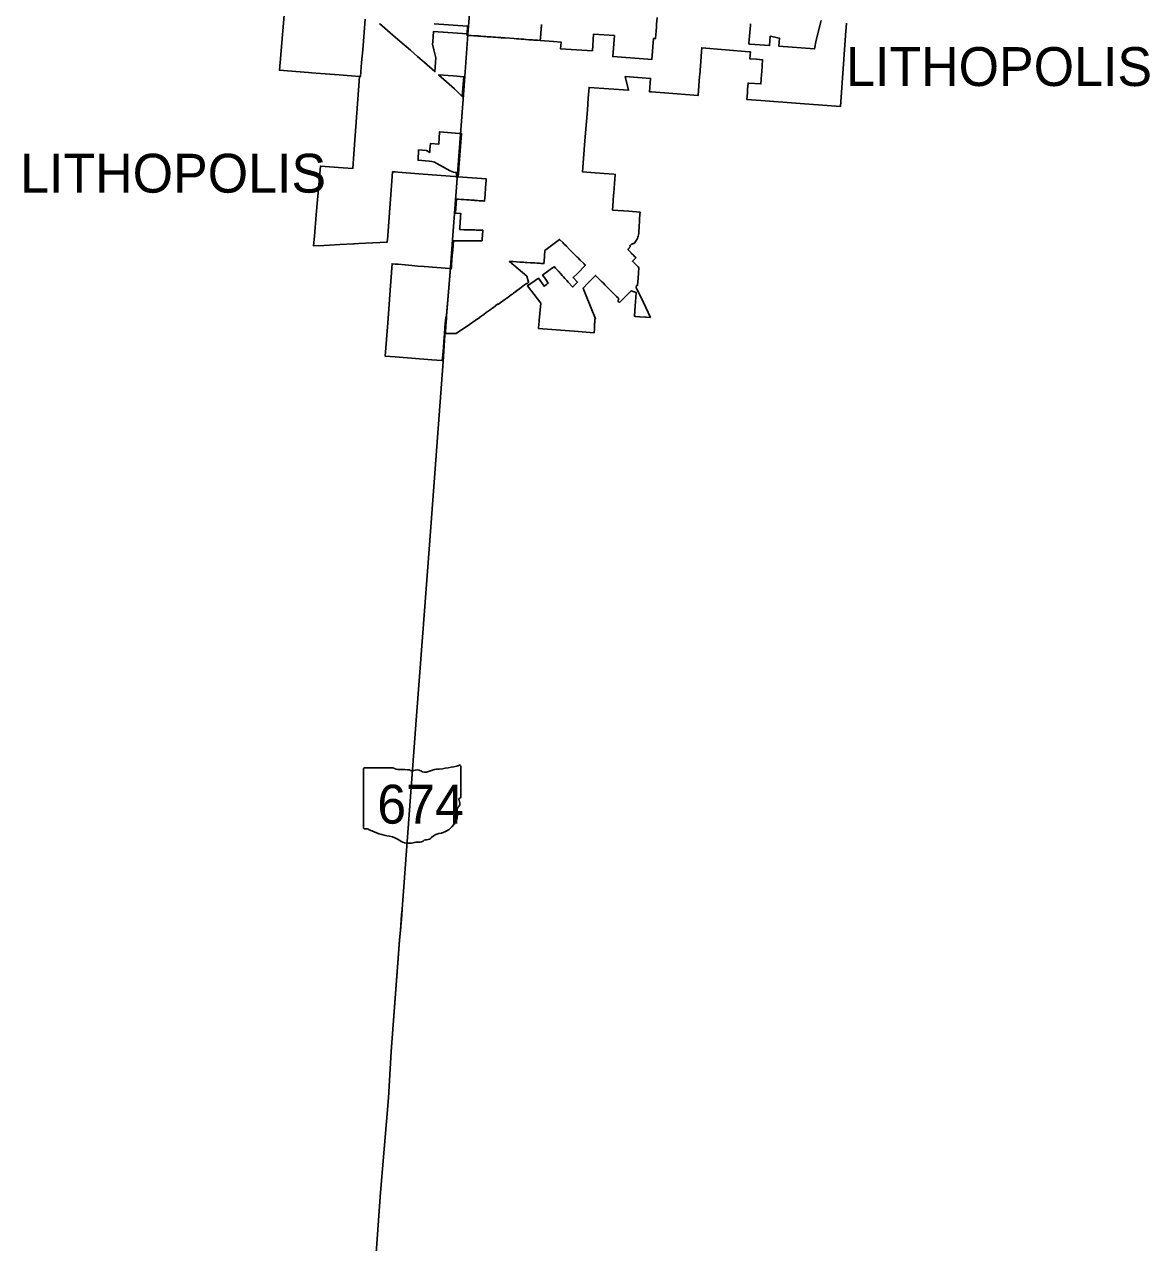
# Model space of a CAD drawing. Extents: x 1801177 to 2073177, y 551183 to 727183.
# Drawn here: x 1865307 to 1897750, y 628489 to 663604 of the extents above; entities that cross this region are included whole.
import ezdxf

# ---------------------------------------------------------------- set-up
doc = ezdxf.new("R2010")
doc.units = 0
for name, color, linetype in [('GM_X_Corporation', 7, 'Continuous'), ('GM_X_Corporation_Text', 7, 'Continuous'), ('GM_X_County', 7, 'Continuous'), ('GM_X_State_Location', 7, 'Continuous'), ('GM_X_State_Route', 7, 'Continuous'), ('GM_X_State_Shield', 7, 'Continuous')]:
    doc.layers.add(name, color=color, linetype=linetype)

msp = doc.modelspace()

# ---------------------------------------------------------------- linework, layer by layer
at = {"layer": 'GM_X_Corporation'}
for points in [[(1875134, 663754), (1875061, 662869), (1875031, 662503), (1874998, 662100), (1874967, 662103), (1874384, 662149), (1873849, 662191), (1873586, 662212), (1873499, 662218), (1872898, 662266), (1872661, 662284), (1872680, 662503), (1872831, 664211)], [(1889006, 663643), (1888980, 663285), (1888833, 661235), (1887677, 661322), (1886542, 661407), (1886138, 661437), (1886152, 661637), (1886160, 661736), (1886172, 661913), (1886186, 661912), (1886541, 661886), (1886561, 662164), (1886567, 662240), (1886592, 662585), (1886420, 662597), (1886223, 662611), (1886231, 662712), (1886238, 662812), (1886220, 662813), (1886208, 662814), (1886208, 662816), (1884836, 662928), (1884829, 662828), (1884817, 662668), (1884778, 662152), (1884776, 662113), (1884734, 661557), (1883761, 661631), (1883392, 661659), (1883362, 661661), (1883332, 661663), (1883360, 662044), (1882633, 662101), (1882726, 661706), (1881588, 661786), (1881564, 661474), (1881539, 661145), (1881470, 660252), (1881402, 659349), (1881762, 659323), (1882026, 659303), (1882299, 659283), (1882342, 659280), (1882323, 659020), (1882312, 658881), (1882311, 658868), (1882304, 658772), (1882297, 658682), (1882285, 658531), (1882284, 658508), (1882264, 658252), (1882264, 658251), (1882732, 658216), (1883057, 658192), (1883052, 658122), (1883043, 658002), (1883038, 657932), (1883042, 657931), (1883041, 657929), (1883046, 657928), (1883036, 657780), (1883023, 657614), (1883023, 657608), (1883019, 657572), (1883013, 657537), (1883004, 657503), (1882994, 657469), (1882981, 657435), (1882966, 657403), (1882949, 657372), (1882930, 657341), (1882908, 657313), (1882885, 657285), (1882874, 657295), (1882855, 657275), (1882848, 657268), (1882831, 657286), (1882781, 657236), (1882760, 657215), (1882778, 657197), (1882740, 657159), (1882743, 657156), (1882714, 657127), (1882717, 657124), (1882706, 657112), (1882723, 657095), (1882741, 657077), (1882770, 657048), (1882803, 657015), (1882806, 657012), (1882865, 656953), (1882892, 656926), (1882927, 656891), (1882939, 656879), (1882836, 656776), (1882999, 656614), (1883022, 656591), (1883011, 656437), (1883000, 656293), (1882985, 656081), (1882960, 656075), (1882949, 656023), (1883157, 655589), (1883358, 655155), (1883242, 655164), (1883230, 655165), (1883217, 655166), (1883056, 655178), (1882924, 655187), (1882894, 655189), (1882916, 655488), (1882925, 655605), (1882945, 655874), (1882801, 655925), (1882790, 655913), (1882731, 655854), (1882673, 655796), (1882638, 655761), (1882521, 655644), (1882515, 655638), (1882509, 655632), (1882472, 655593), (1882424, 655609), (1882433, 655710), (1882382, 655762), (1882101, 656041), (1882090, 656053), (1882063, 656080), (1882043, 656100), (1882003, 656140), (1881996, 656146), (1881990, 656153), (1881950, 656193), (1881910, 656232), (1881903, 656240), (1881775, 656368), (1881590, 656184), (1881541, 656135), (1881418, 656004), (1881448, 655927), (1881490, 655823), (1881770, 655116), (1881757, 655117), (1881751, 655009), (1881749, 654981), (1881741, 654832), (1881735, 654717), (1881163, 654759), (1880768, 654788), (1880134, 654838), (1880143, 654968), (1880148, 655027), (1880152, 655069), (1880168, 655269), (1880193, 655572), (1880193, 655572), (1879815, 656070), (1880127, 656292), (1880292, 656058), (1880359, 656108), (1880389, 656131), (1880395, 656135), (1880412, 656148), (1880412, 656148), (1880342, 656247), (1880301, 656306), (1880249, 656379), (1880281, 656402), (1880426, 656510), (1880507, 656569), (1880551, 656601), (1880581, 656624), (1880621, 656580), (1880656, 656542), (1880693, 656501), (1880698, 656495), (1880733, 656457), (1880745, 656444), (1880757, 656430), (1880760, 656427), (1880768, 656418), (1880773, 656413), (1880814, 656368), (1880854, 656324), (1880894, 656280), (1880938, 656232), (1880948, 656220), (1880989, 656176), (1881115, 656042), (1881122, 656035), (1881151, 656065), (1881190, 656106), (1881223, 656140), (1881257, 656174), (1881254, 656177), (1881128, 656310), (1881250, 656426), (1881483, 656660), (1881448, 656695), (1881435, 656707), (1881331, 656811), (1881261, 656881), (1881249, 656892), (1881061, 657079), (1881026, 657114), (1880934, 657207), (1880865, 657276), (1880841, 657301), (1880829, 657313), (1880736, 657406), (1880316, 657084), (1880292, 656769), (1880288, 656725), (1880287, 656709), (1880195, 656714), (1880155, 656717), (1880147, 656717), (1880136, 656718), (1880095, 656721), (1880013, 656726), (1879995, 656727), (1879951, 656730), (1879895, 656733), (1879796, 656740), (1879790, 656740), (1879744, 656743), (1879696, 656746), (1879654, 656749), (1879630, 656750), (1879596, 656753), (1879496, 656759), (1879396, 656765), (1879297, 656773), (1879294, 656773), (1879790, 656345), (1879844, 656171), (1879846, 656166), (1879821, 656148), (1879785, 656123), (1879783, 656133), (1879731, 656096), (1879678, 656058), (1879588, 655994), (1879495, 655928), (1879501, 655920), (1879413, 655857), (1879379, 655832), (1879356, 655816), (1879281, 655762), (1879264, 655750), (1879257, 655745), (1879146, 655664), (1879136, 655657), (1879135, 655656), (1879116, 655642), (1879109, 655637), (1879095, 655627), (1879025, 655576), (1878974, 655539), (1878968, 655547), (1878900, 655497), (1878894, 655493), (1878831, 655447), (1878789, 655416), (1878762, 655397), (1878722, 655367), (1878694, 655346), (1878675, 655333), (1878625, 655296), (1878556, 655246), (1878471, 655184), (1878382, 655119), (1878372, 655112), (1878075, 654905), (1877797, 654718), (1877756, 654694), (1877446, 654695), (1877452, 654778), (1877452, 654783), (1877458, 654866), (1877462, 654924), (1877469, 655016), (1877476, 655129), (1877478, 655166), (1877454, 655166), (1877445, 655040), (1877442, 655003), (1877417, 654690), (1877399, 654455), (1877387, 654301), (1877378, 654186), (1877363, 653986), (1877357, 653914), (1877348, 653915), (1877052, 653937), (1875999, 654017), (1875714, 654039), (1875785, 655003), (1875862, 656064), (1875871, 656190), (1875908, 656703), (1875999, 656696), (1876085, 656688), (1876285, 656671), (1876482, 656654), (1876656, 656639), (1876832, 656625), (1877562, 656567), (1877616, 656563), (1877619, 656598), (1877622, 656644), (1877626, 656698), (1877633, 656783), (1877634, 656797), (1877645, 656947), (1877657, 657097), (1877678, 657368), (1877949, 657368), (1878049, 657368), (1878149, 657368), (1878250, 657367), (1878351, 657367), (1878451, 657367), (1878505, 657367), (1878509, 657428), (1878514, 657517), (1878524, 657672), (1878423, 657675), (1878396, 657675), (1878374, 657676), (1878348, 657676), (1878340, 657677), (1878294, 657678), (1878287, 657678), (1878274, 657678), (1878214, 657679), (1878199, 657680), (1878134, 657681), (1878124, 657681), (1878054, 657683), (1878049, 657683), (1878001, 657684), (1877974, 657685), (1877856, 657687), (1877858, 657716), (1877860, 657746), (1877861, 657755), (1877870, 657883), (1877872, 657915), (1877873, 657920), (1877875, 657955), (1877877, 657984), (1877878, 657994), (1877884, 658074), (1877890, 658154), (1877848, 658156), (1877746, 658160), (1877738, 658160), (1877736, 658160), (1877767, 658568), (1877777, 658567), (1877814, 658565), (1877825, 658564), (1877893, 658559), (1877925, 658557), (1877973, 658554), (1878053, 658548), (1878055, 658548), (1878133, 658543), (1878177, 658539), (1878213, 658537), (1878274, 658533), (1878292, 658532), (1878372, 658526), (1878423, 658522), (1878452, 658520), (1878493, 658518), (1878532, 658515), (1878575, 658512), (1878576, 658530), (1878581, 658592), (1878589, 658704), (1878594, 658768), (1878599, 658827), (1878599, 658835), (1878605, 658916), (1878612, 659000), (1878621, 659120), (1878623, 659150), (1877815, 659206), (1877832, 659423), (1877836, 659483), (1877837, 659493), (1877845, 659592), (1877854, 659706), (1877911, 660458), (1877882, 660460), (1877853, 660462), (1877280, 660507), (1877266, 660327), (1877252, 660149), (1877013, 660169), (1877000, 660003), (1876993, 659908), (1876906, 659969), (1876674, 659987), (1876659, 659687), (1876981, 659663), (1877056, 659651), (1877128, 659629), (1877197, 659597), (1877581, 659380), (1877628, 659360), (1877677, 659344), (1877727, 659335), (1877767, 659332), (1877763, 659272), (1877758, 659214), (1877716, 659216), (1876804, 659287), (1876072, 659344), (1875999, 659350), (1875922, 659356), (1875785, 657521), (1875784, 657503), (1875771, 657331), (1874939, 657289), (1874830, 657283), (1874797, 657281), (1874402, 657259), (1874108, 657243), (1873937, 657234), (1873645, 657218), (1873669, 657503), (1873722, 658119), (1873841, 659518), (1874494, 659467), (1874774, 659445), (1874814, 660003), (1874967, 662103), (1874998, 662100), (1875031, 662503), (1875061, 662869), (1875134, 663754)], [(1875545, 663630), (1875934, 663293), (1875999, 663237), (1876137, 663117), (1876438, 662856), (1876640, 662681), (1876775, 662563), (1876845, 662503), (1877144, 662243), (1877159, 662503), (1877169, 662642), (1877117, 662866), (1877077, 663037), (1877082, 663101), (1877106, 663399), (1878071, 663331), (1878068, 663293), (1878101, 663289), (1878115, 663288), (1878131, 663287), (1878146, 663286), (1878191, 663283), (1878262, 663277), (1878299, 663275), (1878332, 663272), (1878379, 663269), (1878401, 663267), (1878421, 663266), (1878471, 663262), (1878541, 663257), (1878551, 663257), (1878611, 663252), (1878652, 663249), (1878681, 663247), (1878722, 663244), (1878750, 663242), (1878770, 663241), (1878820, 663237), (1878890, 663232), (1878895, 663232), (1878960, 663227), (1878999, 663224), (1879030, 663222), (1879065, 663220), (1879100, 663217), (1879124, 663215), (1879169, 663212), (1879425, 663194), (1879495, 663189), (1879500, 663188), (1879564, 663184), (1879564, 663184), (1879635, 663179), (1879635, 663179), (1879670, 663176), (1879704, 663174), (1879755, 663170), (1879774, 663169), (1879849, 663163), (1879924, 663158), (1879959, 663155), (1879999, 663152), (1880100, 663145), (1880183, 663139), (1880565, 663112), (1880780, 663096), (1880765, 662899), (1881228, 662871), (1881683, 662844), (1881718, 663326), (1882318, 663281), (1882273, 662677), (1883284, 662601), (1883401, 662593), (1883446, 663197), (1883458, 663196), (1883476, 663194), (1883499, 663192), (1883506, 663192), (1883516, 663325), (1883522, 663396), (1883533, 663542), (1883537, 663599), (1883552, 663803)], [(1886243, 663622), (1886240, 663580), (1886215, 663267), (1886199, 663066), (1886198, 663043), (1886225, 663035), (1886793, 662993), (1886813, 663262), (1886945, 663237), (1887071, 663204), (1887081, 663202), (1887064, 662973), (1888089, 662898), (1888138, 663147), (1888281, 663719)], [(1880218, 663605), (1880216, 663571), (1880213, 663535), (1880211, 663509), (1880207, 663465), (1880203, 663406), (1880202, 663396), (1880202, 663387), (1880197, 663326), (1880197, 663326), (1880183, 663139), (1880183, 663139), (1880100, 663145), (1879999, 663152), (1879959, 663155), (1879924, 663158), (1879849, 663163), (1879774, 663169), (1879755, 663170), (1879704, 663174), (1879670, 663176), (1879635, 663179), (1879564, 663184), (1879500, 663188), (1879495, 663189), (1879425, 663194), (1879169, 663212), (1879124, 663215), (1879100, 663217), (1879065, 663220), (1879030, 663222), (1878999, 663224), (1878960, 663227), (1878895, 663232), (1878890, 663232), (1878820, 663237), (1878770, 663241), (1878750, 663242), (1878722, 663244), (1878681, 663247), (1878652, 663249), (1878611, 663252), (1878551, 663257), (1878541, 663257), (1878471, 663262), (1878421, 663266), (1878401, 663267), (1878379, 663269), (1878332, 663272), (1878299, 663275), (1878262, 663277), (1878191, 663283), (1878146, 663286), (1878131, 663287), (1878115, 663288), (1878101, 663289), (1878068, 663293), (1878071, 663331), (1878088, 663550), (1877124, 663623)]]:
    msp.add_lwpolyline(points, dxfattribs=at)
msp.add_lwpolyline([(1877249, 662154), (1877710, 661749), (1877931, 661523), (1877948, 661762), (1877974, 662091), (1877674, 662117)], close=True, dxfattribs=at)
at = {"layer": 'GM_X_County'}
msp.add_lwpolyline([(1875413, 627659), (1875576, 629935), (1875802, 632665), (1875882, 633999), (1876078, 636560), (1876123, 637214), (1876147, 637492), (1876185, 637933), (1876197, 638101), (1876583, 643288), (1876602, 643553), (1876784, 645940), (1876988, 648603), (1877383, 653890), (1877432, 654644), (1877590, 656583), (1877648, 657396), (1877956, 661453), (1877983, 661831), (1878095, 663314), (1878188, 664507)], dxfattribs=at)
at = {"layer": 'GM_X_State_Route'}
msp.add_line((1877880, 660436), (1877958, 661450), dxfattribs=at)
for points in [[(1877593, 656606), (1877649, 657393), (1877880, 660436)], [(1877478, 655195), (1877591, 656580), (1877593, 656606)], [(1877384, 653888), (1877433, 654641), (1877478, 655195)], [(1876603, 643550), (1876786, 645937), (1876989, 648600), (1877384, 653888)], [(1875414, 627656), (1875577, 629933), (1875803, 632662), (1875883, 633996), (1876079, 636557), (1876124, 637211), (1876148, 637489), (1876186, 637930), (1876198, 638099), (1876584, 643285), (1876603, 643550)]]:
    msp.add_lwpolyline(points, dxfattribs=at)
at = {"layer": 'GM_X_State_Shield'}
for p, q in [((1875086, 642148), (1875086, 640446)), ((1875934, 642177), (1875113, 642177)), ((1877887, 641329), (1877887, 642219)), ((1877887, 641329), (1877887, 641329))]:
    msp.add_line(p, q, dxfattribs=at)
for centre, major_axis, start_param, end_param in [((1875118, 642151), (32.5, 0), 1.712693, 3.28349), ((1876129, 642374), (315, 0), 4.042523, 4.731795), ((1876234, 641222), (1130, 0), 1.404758, 1.657858), ((1876490, 642160), (90.8, 0), 3.836095, 5.185415), ((1876623, 641963), (189, 0), 0.950623, 2.079405), ((1876867, 642233), (227, 0), 4.081561, 5.145723), ((1877268, 641657), (598, 0), 1.699011, 2.107814), ((1876889, 644496), (2971, 0), 4.814394, 5.042369), ((1877856, 642223), (31.2, 0), 6.141152, 7.989035), ((1877880, 641264), (48.3, 0), 1.883978, 3.671073), ((1877573, 641151), (290, 0), 5.934695, 6.695948), ((1877854, 641326), (33.4, 0), 5.05454, 6.418171), ((1877056, 640844), (743, 0), 5.101752, 6.440018), ((1877999, 640957), (211, 0), 2.387724, 3.262537), ((1875118, 640443), (32.7, 0), 3.00124, 4.508301), ((1875123, 640617), (250, 0), 4.665946, 4.897461), ((1875174, 640348), (90.1, 0), 0.519207, 1.627899), ((1876312, 641877), (2146, 0), 4.195997, 4.488961), ((1875672, 639682), (671, 0), 0.823519, 1.323587), ((1876853, 640282), (240, 0), 4.937069, 5.64225), ((1877369, 639969), (407, 0), 1.647645, 2.488434), ((1876398, 640340), (426, 0), 4.026481, 4.996735), ((1876644, 639752), (350, 0), 1.495662, 1.94098), ((1876675, 640212), (227, 0), 4.691044, 5.507374), ((1876881, 640048), (63.9, 0), 1.147584, 2.315152)]:
    msp.add_ellipse(centre, major_axis=major_axis, ratio=0.8, start_param=start_param, end_param=end_param, dxfattribs=at)

# ---------------------------------------------------------------- texts
at = {"layer": 'GM_X_Corporation_Text'}
for p in [(1888997, 661828), (1865184, 658754)]:
    msp.add_text('LITHOPOLIS', height=1120, rotation=0, dxfattribs=at).set_placement(p)
at = {"layer": 'GM_X_State_Location'}
for s in ['s', 'r']:
    msp.add_text(s, height=1, dxfattribs=at).set_placement((1876443, 641238))
msp.add_text('674', height=1, rotation=0, dxfattribs=at).set_placement((1876090, 641165))
at = {"layer": 'GM_X_State_Shield'}
msp.add_text('674', height=1120.7, dxfattribs=at).set_placement((1875481, 640566))

doc.saveas('drawing.dxf')
